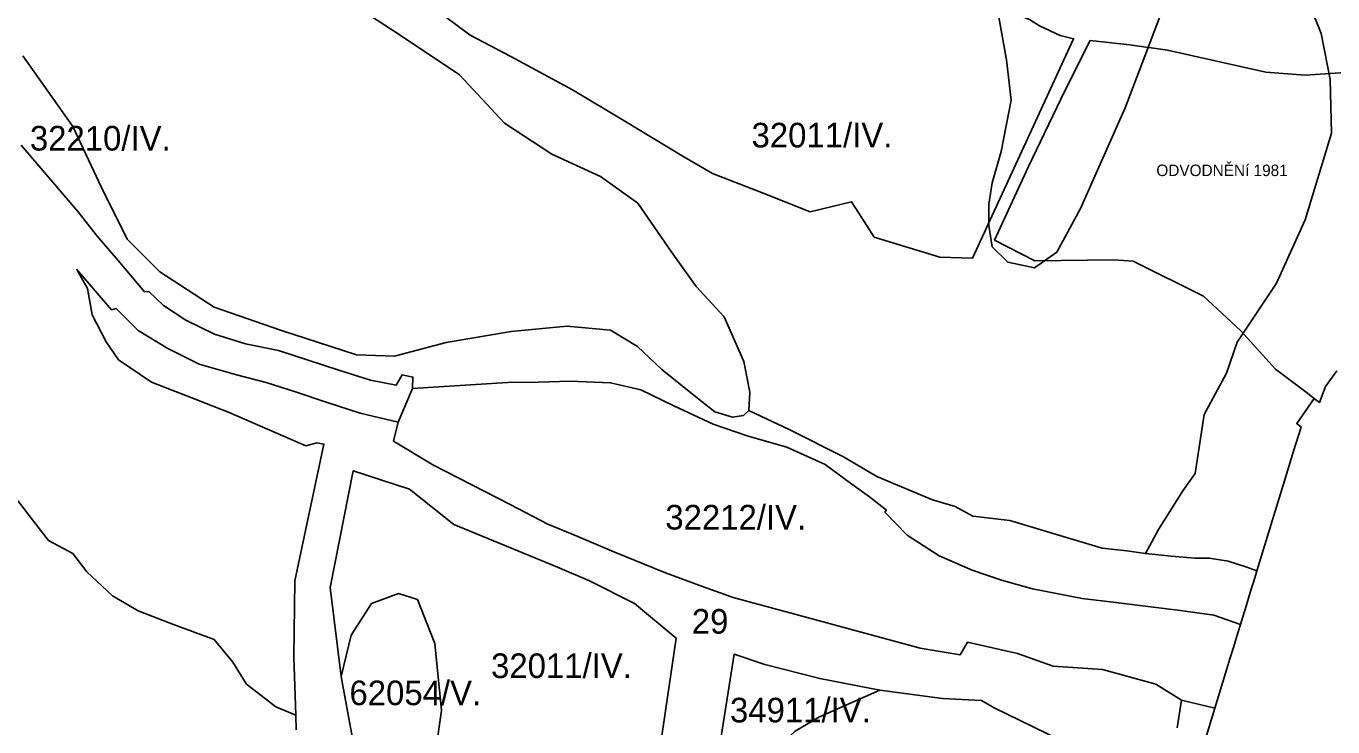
# Model space of a CAD drawing. Extents: x -521621 to -516761, y -1190184 to -1184927.
# Drawn here: x -518211 to -517414, y -1188092 to -1187665 of the extents above; entities that cross this region are included whole.
import ezdxf

# ---------------------------------------------------------------- set-up
doc = ezdxf.new("R2010")
doc.units = 0
doc.layers.add('BPEJ_s', color=7, linetype='Continuous')
doc.layers.add('odvodneni_s', color=7, linetype='Continuous')

msp = doc.modelspace()

# ---------------------------------------------------------------- linework, layer by layer
at = {"layer": 'BPEJ_s'}
for p, q in [((-518213.64, -1187737.85), (-518179.13, -1187778.41)), ((-518179.13, -1187778.41), (-518167.09, -1187793.48)), ((-518167.09, -1187793.48), (-518154.41, -1187808.16)), ((-518154.41, -1187808.16), (-518138.39, -1187827.34)), ((-518158.47, -1187838.17), (-518179.66, -1187813.57)), ((-518179.66, -1187813.57), (-518173.12, -1187825.31)), ((-518173.12, -1187825.31), (-518170.41, -1187841.33)), ((-518138.39, -1187827.34), (-518135.81, -1187827.06)), ((-518135.81, -1187827.06), (-518126.94, -1187835.65)), ((-518170.41, -1187841.33), (-518161.85, -1187857.8)), ((-518155.76, -1187837.49), (-518158.47, -1187838.17)), ((-518142.23, -1187850.8), (-518155.76, -1187837.49)), ((-518126.94, -1187835.65), (-518113.21, -1187844.53)), ((-518113.21, -1187844.53), (-518095.75, -1187853.12)), ((-518161.85, -1187857.8), (-518154.18, -1187868.63)), ((-518124.19, -1187861.86), (-518142.23, -1187850.8)), ((-518095.75, -1187853.12), (-518076.87, -1187858.85)), ((-518105.03, -1187871.34), (-518124.19, -1187861.86)), ((-518076.87, -1187858.85), (-518056.84, -1187863)), ((-518056.84, -1187863), (-518019.92, -1187875.03)), ((-518154.18, -1187868.63), (-518134.11, -1187882.17)), ((-518082.26, -1187877.88), (-518105.03, -1187871.34)), ((-518134.11, -1187882.17), (-518112.24, -1187890.75)), ((-518064.22, -1187882.4), (-518082.26, -1187877.88)), ((-518019.92, -1187875.03), (-518000.61, -1187881.04)), ((-518000.61, -1187881.04), (-517985.01, -1187884.05)), ((-517985.01, -1187884.05), (-517981.29, -1187877.89)), ((-517981.29, -1187877.89), (-517974.85, -1187879.18)), ((-517974.85, -1187879.18), (-517975.14, -1187886.06)), ((-518046.39, -1187888.2), (-518064.22, -1187882.4)), ((-518027.65, -1187894.51), (-518046.39, -1187888.2)), ((-517975.14, -1187886.06), (-517983.72, -1187906.53)), ((-518112.24, -1187890.75), (-518086.88, -1187900.67)), ((-518006.9, -1187901.24), (-518027.65, -1187894.51)), ((-518086.88, -1187900.67), (-518039.99, -1187921.04)), ((-517983.72, -1187906.53), (-518006.9, -1187901.24)), ((-518029.09, -1187919.95), (-518046.87, -1188003.31)), ((-518039.99, -1187921.04), (-518033.45, -1187919.22)), ((-518033.45, -1187919.22), (-518029.09, -1187919.95)), ((-518206.66, -1187966.08), (-518219.21, -1187949.69)), ((-518196.87, -1187978.64), (-518206.66, -1187966.08)), ((-518182.2, -1187986.52), (-518196.87, -1187978.64)), ((-518173.59, -1187997.71), (-518182.2, -1187986.52)), ((-518157.98, -1188012.41), (-518173.59, -1187997.71)), ((-518046.87, -1188003.31), (-518047.36, -1188049.86)), ((-518142.37, -1188021.59), (-518157.98, -1188012.41)), ((-518120.8, -1188029.86), (-518142.37, -1188021.59)), ((-518096.01, -1188039.05), (-518120.8, -1188029.86)), ((-518084.53, -1188052.83), (-518096.01, -1188039.05)), ((-518076.27, -1188066.15), (-518084.53, -1188052.83)), ((-518047.36, -1188049.86), (-518046.19, -1188085.08)), ((-518058.36, -1188079.93), (-518076.27, -1188066.15)), ((-518046.19, -1188085.08), (-518058.36, -1188079.93))]:
    msp.add_line(p, q, dxfattribs=at)
for points in [[(-517439.63, -1187623.44), (-517421.23, -1187669.85), (-517415.64, -1187697.86), (-517414.84, -1187730.67), (-517430.83, -1187783.49), (-517448.42, -1187821.9), (-517472.41, -1187857.91), (-517478.78, -1187876.76), (-517492.39, -1187901.92), (-517498, -1187937.94), (-517501.04, -1187942.11), (-517505.43, -1187948.44), (-517520.28, -1187972.09), (-517528.25, -1187986.67), (-517539.52, -1187985.02), (-517554.63, -1187983.37), (-517586.52, -1187973.74), (-517610.98, -1187966.59), (-517633.52, -1187963.84), (-517644.24, -1187958.06), (-517657.98, -1187953.94), (-517692.06, -1187939.64), (-517712.4, -1187927.81), (-517745.11, -1187911.31), (-517770.12, -1187899.48), (-517769.43, -1187888.42), (-517772.99, -1187869.58), (-517785.06, -1187842.57), (-517802.11, -1187824.08), (-517817.39, -1187802.76), (-517837.64, -1187773.26), (-517860.37, -1187756.91), (-517890.21, -1187743.4), (-517918.98, -1187724.56), (-517946.33, -1187695.06), (-517983.27, -1187670.54), (-518000.68, -1187659.17)], [(-517411.5, -1187875.42), (-517418.52, -1187884.86), (-517420.63, -1187890.38), (-517422.24, -1187894.57), (-517425.48, -1187892.14), (-517435.99, -1187907.52), (-517433.4, -1187909.62), (-517435.14, -1187915.28), (-517437.93, -1187924.35), (-517444.26, -1187945), (-517460.27, -1187997.18), (-517467.02, -1187994.67), (-517477.76, -1187991.33), (-517489.25, -1187989.48), (-517498.14, -1187989.48), (-517512.58, -1187988.32), (-517528.25, -1187986.67), (-517520.28, -1187972.09), (-517505.43, -1187948.44), (-517501.04, -1187942.11), (-517498, -1187937.94), (-517492.39, -1187901.92), (-517478.78, -1187876.76), (-517472.41, -1187857.91), (-517448.42, -1187821.9), (-517430.83, -1187783.49), (-517414.84, -1187730.67), (-517415.64, -1187697.86), (-517421.23, -1187669.85), (-517439.63, -1187623.44)], [(-517617.66, -1187660.01), (-517612.9, -1187685.91), (-517610.17, -1187710.45), (-517616.3, -1187741.8), (-517621.75, -1187760.89), (-517623.8, -1187773.84), (-517623.8, -1187786.79), (-517621.75, -1187799.74), (-517612.22, -1187809.28), (-517595.87, -1187812.69), (-517582.24, -1187803.15), (-517567.94, -1187776.56), (-517540.69, -1187715.22), (-517518.21, -1187656.6)], [(-517518.21, -1187656.6), (-517540.69, -1187715.22), (-517567.94, -1187776.56), (-517582.24, -1187803.15), (-517595.87, -1187812.69), (-517612.22, -1187809.28), (-517621.75, -1187799.74), (-517623.8, -1187786.79), (-517623.8, -1187773.84), (-517621.75, -1187760.89), (-517616.3, -1187741.8), (-517610.17, -1187710.45), (-517612.9, -1187685.91), (-517617.66, -1187660.01)], [(-518000.68, -1187659.17), (-517983.27, -1187670.54), (-517946.33, -1187695.06), (-517918.98, -1187724.56), (-517890.21, -1187743.4), (-517860.37, -1187756.91), (-517837.64, -1187773.26), (-517817.39, -1187802.76), (-517802.11, -1187824.08), (-517785.06, -1187842.57), (-517772.99, -1187869.58), (-517769.43, -1187888.42), (-517770.12, -1187899.48), (-517773.34, -1187902.63), (-517780.01, -1187903.61), (-517790.77, -1187900.3), (-517802.35, -1187891.19), (-517823.03, -1187874.64), (-517837.92, -1187860.57), (-517854.46, -1187850.63), (-517880.93, -1187848.15), (-517914.85, -1187851.46), (-517954.55, -1187858.08), (-517985.99, -1187866.36), (-518009.15, -1187865.53), (-518055.47, -1187850.63), (-518096.01, -1187836.56), (-518129.09, -1187815.04), (-518148.95, -1187795.18), (-518164.66, -1187763.72), (-518182.04, -1187726.48), (-518212.64, -1187683.44)], [(-518212.64, -1187683.44), (-518182.04, -1187726.48), (-518164.66, -1187763.72), (-518148.95, -1187795.18), (-518129.09, -1187815.04), (-518096.01, -1187836.56), (-518055.47, -1187850.63), (-518009.15, -1187865.53), (-517985.99, -1187866.36), (-517954.55, -1187858.08), (-517914.85, -1187851.46), (-517880.93, -1187848.15), (-517854.46, -1187850.63), (-517837.92, -1187860.57), (-517823.03, -1187874.64), (-517802.35, -1187891.19), (-517790.77, -1187900.3), (-517780.01, -1187903.61), (-517773.34, -1187902.63), (-517770.12, -1187899.48), (-517745.11, -1187911.31), (-517712.4, -1187927.81), (-517692.06, -1187939.64), (-517657.98, -1187953.94), (-517644.24, -1187958.06), (-517633.52, -1187963.84), (-517610.98, -1187966.59), (-517586.52, -1187973.74), (-517554.63, -1187983.37), (-517539.52, -1187985.02), (-517528.25, -1187986.67), (-517512.58, -1187988.32), (-517498.14, -1187989.48), (-517489.25, -1187989.48), (-517477.76, -1187991.33), (-517467.02, -1187994.67), (-517460.27, -1187997.18), (-517460.97, -1187999.46), (-517462.6, -1188004.76), (-517462.68, -1188004.99), (-517462.75, -1188005.22), (-517463.55, -1188007.83), (-517464.35, -1188010.44), (-517467.53, -1188020.76), (-517468.1, -1188022.61), (-517470.32, -1188029.84), (-517486.54, -1188024.11), (-517506.82, -1188021.25), (-517526.82, -1188018.96), (-517546.24, -1188016.39), (-517566.8, -1188014.1), (-517597.08, -1188008.1), (-517615.93, -1188002.96), (-517633.93, -1187996.84), (-517654.1, -1187988.05), (-517673.55, -1187975.47), (-517687.08, -1187961.46), (-517686.13, -1187960.27), (-517696.57, -1187952.2), (-517707.24, -1187944.36), (-517723.51, -1187932.46), (-517746.77, -1187921.95), (-517770.52, -1187915.2), (-517791.77, -1187907.94), (-517815.77, -1187896.68), (-517835.78, -1187886.92), (-517854.28, -1187882.67), (-517878.94, -1187881.73), (-517898.5, -1187882.27), (-517917.15, -1187882.45), (-517975.14, -1187886.06), (-517974.85, -1187879.18), (-517981.29, -1187877.89), (-517985.01, -1187884.05), (-518000.61, -1187881.04), (-518019.92, -1187875.03), (-518056.84, -1187863), (-518076.87, -1187858.85), (-518095.75, -1187853.12), (-518113.21, -1187844.53), (-518126.94, -1187835.65), (-518135.81, -1187827.06), (-518138.39, -1187827.34), (-518154.41, -1187808.16), (-518167.09, -1187793.48), (-518179.13, -1187778.41), (-518213.64, -1187737.85)], [(-518045.9, -1188093.97), (-518046.19, -1188085.08), (-518047.36, -1188049.86), (-518046.87, -1188003.31), (-518029.09, -1187919.95), (-518033.45, -1187919.22), (-518039.99, -1187921.04), (-518086.88, -1187900.67), (-518112.24, -1187890.75), (-518134.11, -1187882.17), (-518154.18, -1187868.63), (-518161.85, -1187857.8), (-518170.41, -1187841.33), (-518173.12, -1187825.31), (-518179.66, -1187813.57), (-518158.47, -1187838.17), (-518155.76, -1187837.49), (-518142.23, -1187850.8), (-518124.19, -1187861.86), (-518105.03, -1187871.34), (-518082.26, -1187877.88), (-518064.22, -1187882.4), (-518046.39, -1187888.2), (-518027.65, -1187894.51), (-518006.9, -1187901.24), (-517983.72, -1187906.53), (-517986.73, -1187918.13), (-517962.73, -1187932.64), (-517915.07, -1187957.04), (-517892.64, -1187968.68), (-517874.24, -1187976.3), (-517852.24, -1187985.62), (-517820.93, -1187998.32), (-517798.3, -1188006.79), (-517779.68, -1188013.35), (-517732.15, -1188026.28), (-517665.49, -1188044.33), (-517641.29, -1188048.36), (-517636.78, -1188040.69), (-517606.22, -1188047.55), (-517584.51, -1188055.27), (-517554.52, -1188057.27), (-517521.96, -1188066.13), (-517506.25, -1188075.85), (-517508.82, -1188092.71)], [(-517960.81, -1188106.35), (-517957.37, -1188082.23), (-517961.5, -1188041.34), (-517972.06, -1188014.7), (-517983.54, -1188011.03), (-518000.06, -1188017), (-518012.46, -1188036.29), (-518018.47, -1188061.62), (-518025.33, -1188007.23), (-518011.13, -1187936.17), (-517976.85, -1187947.44), (-517949.92, -1187969), (-517886.76, -1187994.97), (-517867.17, -1188003.31), (-517839.75, -1188017.03), (-517814.29, -1188038.1), (-517833.89, -1188171.06)], [(-517833.89, -1188171.06), (-517814.29, -1188038.1), (-517839.75, -1188017.03), (-517867.17, -1188003.31), (-517886.76, -1187994.97), (-517949.92, -1187969), (-517976.85, -1187947.44), (-518011.13, -1187936.17), (-518025.33, -1188007.23), (-518018.47, -1188061.62), (-518002.81, -1188146.9)], [(-518219.21, -1187949.69), (-518206.66, -1187966.08), (-518196.87, -1187978.64), (-518182.2, -1187986.52), (-518173.59, -1187997.71), (-518157.98, -1188012.41), (-518142.37, -1188021.59), (-518120.8, -1188029.86), (-518096.01, -1188039.05), (-518084.53, -1188052.83), (-518076.27, -1188066.15), (-518058.36, -1188079.93), (-518046.19, -1188085.08), (-518045.9, -1188093.97)], [(-517580.51, -1188100.15), (-517620.48, -1188080.59), (-517628.22, -1188076.12), (-517652.05, -1188074.93), (-517690.18, -1188069.86), (-517726.82, -1188062.71), (-517760.33, -1188054.17), (-517778.93, -1188047.85), (-517795.95, -1188155.97)], [(-517741.81, -1188094.89), (-517726.97, -1188086.09), (-517690.18, -1188069.86), (-517652.05, -1188074.93), (-517628.22, -1188076.12), (-517620.48, -1188080.59), (-517580.51, -1188100.15)], [(-517508.82, -1188092.71), (-517506.25, -1188075.85), (-517485.94, -1188080.73), (-517500.67, -1188128.84)]]:
    msp.add_lwpolyline(points, dxfattribs=at)
for points in [[(-517983.72, -1187906.53), (-517975.14, -1187886.06), (-517917.15, -1187882.45), (-517898.5, -1187882.27), (-517878.94, -1187881.73), (-517854.28, -1187882.67), (-517835.78, -1187886.92), (-517815.77, -1187896.68), (-517791.77, -1187907.94), (-517770.52, -1187915.2), (-517746.77, -1187921.95), (-517723.51, -1187932.46), (-517707.24, -1187944.36), (-517696.57, -1187952.2), (-517686.13, -1187960.27), (-517687.08, -1187961.46), (-517673.55, -1187975.47), (-517654.1, -1187988.05), (-517633.93, -1187996.84), (-517615.93, -1188002.96), (-517597.08, -1188008.1), (-517566.8, -1188014.1), (-517546.24, -1188016.39), (-517526.82, -1188018.96), (-517506.82, -1188021.25), (-517486.54, -1188024.11), (-517470.32, -1188029.84), (-517470.7, -1188031.07), (-517470.92, -1188031.77), (-517471.13, -1188032.47), (-517471.52, -1188033.71), (-517471.9, -1188034.95), (-517474.43, -1188043.17), (-517476.96, -1188051.38), (-517477.28, -1188052.43), (-517477.6, -1188053.48), (-517477.81, -1188054.16), (-517478.02, -1188054.84), (-517485.94, -1188080.73), (-517506.25, -1188075.85), (-517521.96, -1188066.13), (-517554.52, -1188057.27), (-517584.51, -1188055.27), (-517606.22, -1188047.55), (-517636.78, -1188040.69), (-517641.29, -1188048.36), (-517665.49, -1188044.33), (-517732.15, -1188026.28), (-517779.68, -1188013.35), (-517798.3, -1188006.79), (-517820.93, -1187998.32), (-517852.24, -1187985.62), (-517874.24, -1187976.3), (-517892.64, -1187968.68), (-517915.07, -1187957.04), (-517962.73, -1187932.64), (-517986.73, -1187918.13)], [(-518018.47, -1188061.62), (-518012.46, -1188036.29), (-518000.06, -1188017), (-517983.54, -1188011.03), (-517972.06, -1188014.7), (-517961.5, -1188041.34), (-517957.37, -1188082.23), (-517960.81, -1188106.35), (-517961.5, -1188111.16), (-517967.47, -1188132.29), (-517977.11, -1188146.99), (-517984.45, -1188150.67), (-517994.55, -1188151.13), (-518000.98, -1188147.91), (-518002.81, -1188146.9)], [(-517795.95, -1188155.97), (-517778.93, -1188047.85), (-517760.33, -1188054.17), (-517726.82, -1188062.71), (-517690.18, -1188069.86), (-517726.97, -1188086.09), (-517741.81, -1188094.89), (-517747.31, -1188099.84), (-517769.3, -1188122.39), (-517781.39, -1188140.55)]]:
    msp.add_lwpolyline(points, close=True, dxfattribs=at)
at = {"layer": 'odvodneni_s'}
for points in [[(-517940, -1187670.92), (-517962.84, -1187653.94)], [(-517620.95, -1187653.19), (-517598.93, -1187661.48), (-517592.76, -1187665.26), (-517580.33, -1187671.15), (-517572.04, -1187673.09), (-517601.22, -1187736.39), (-517633.65, -1187806.72), (-517653.69, -1187806.18), (-517693.66, -1187793.99)], [(-517915.16, -1187683.88), (-517940, -1187670.92)], [(-517411.5, -1187875.42), (-517418.52, -1187884.86), (-517420.63, -1187890.38), (-517422.24, -1187894.57), (-517425.48, -1187892.14), (-517430.23, -1187888.28), (-517449.06, -1187874.4), (-517470.2, -1187850.94), (-517492.89, -1187829.8), (-517535.79, -1187808.65), (-517547.52, -1187807.73), (-517595.67, -1187808.34), (-517620.19, -1187795.76), (-517599.53, -1187750.9), (-517577.46, -1187704.91), (-517562.02, -1187674.2), (-517537.86, -1187676.87), (-517514.84, -1187680), (-517454.78, -1187693.54), (-517430.92, -1187695.29), (-517400.34, -1187693.17)], [(-517877.58, -1187704.18), (-517915.16, -1187683.88)], [(-517845.56, -1187723.31), (-517877.58, -1187704.18)], [(-517810.68, -1187744.45), (-517845.56, -1187723.31)], [(-517792.16, -1187755.26), (-517810.68, -1187744.45)], [(-517762.3, -1187766.83), (-517792.16, -1187755.26)], [(-517732.59, -1187778.56), (-517762.3, -1187766.83)], [(-517707.51, -1187772.39), (-517732.59, -1187778.56)], [(-517703.05, -1187779.35), (-517707.51, -1187772.39)], [(-517693.66, -1187793.99), (-517703.05, -1187779.35)]]:
    msp.add_lwpolyline(points, dxfattribs=at)

# ---------------------------------------------------------------- texts
at = {"layer": 'BPEJ_s'}
for s, p in [('32210/IV.', (-518208.3, -1187741.19)), ('32011/IV.', (-517768.39, -1187739.31)), ('32212/IV.', (-517820.94, -1187972.02)), ('29', (-517804.8, -1188035.46)), ('32011/IV.', (-517927.17, -1188062.48)), ('62054/V.', (-518013.49, -1188079)), ('34911/IV.', (-517781.53, -1188089.51))]:
    msp.add_text(s, height=15, dxfattribs=at).set_placement(p)
at = {"layer": 'odvodneni_s'}
msp.add_text('ODVODNĚNí 1981', height=7, dxfattribs=at).set_placement((-517521.63, -1187756.75))

doc.saveas('drawing.dxf')
